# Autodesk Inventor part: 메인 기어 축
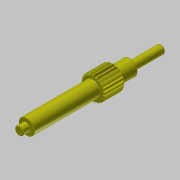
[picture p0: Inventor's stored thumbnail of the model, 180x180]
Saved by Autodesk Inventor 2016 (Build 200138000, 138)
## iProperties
Created: 2018-12
Part Number: 메인 기어 축
Material: 강철, 연강
Document SubType Name: Modeling
Designer: mduedu
Categories: <?xml version="1.0" encoding="UTF-16"?> <MemberInstance><Categories><FamilyTemplate><FamilyTemplateParameter ValueType="xs:double" Id="1" ObjectReferenceKey="da
Density: 7.86 g/cm^3
Appearance: 노란색
Mass: 179.676 g
Surface Area: 75.4119 cm^2
Volume: 22.8595 cm^3
CustomPartVersion: 1
Author: mduedu
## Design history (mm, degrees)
sketch "Sketch1"
  geometry: C1 r 11.3 at (0, 0)
  constraints: 1 centre point
  dimensions: "d0" = 22.6 diameter of C1 (= da_da)
extrude "Extrusion1" new body sketch "Sketch1" distance "d1" = 20 (= da_b); taper "d2" = 0 deg
workplane "Work Plane2"
sketch "Sketch2"
  geometry: C1 r 11.3 at (0, 0) reference; C2 r 10.5 at (0, 0)
  constraints: 1 centre point, 1 coincident
  dimensions: "d3" = 21 diameter of C2 (= da_dw)
feature "피치 지름" sketch "Sketch2" dims "d4" = 10, "d5" = 0
workplane "Work Plane8"
workplane "Work Plane9"
chamfer "모따기1" distance "d49" = 1; stored, may be unused: second distance "d50" = 2, angle "d51" = 45 deg
sketch "스케치3"
  geometry: C1 r 7.5 at (0, 0); 1 further point
  constraints: 1 centre point, 1 coincident
  dimensions: "d52" = 15 diameter of C1
extrude "돌출2" join sketch "스케치3" distance "d53" = 64; taper "d54" = 0 deg
sketch "스케치4"
  geometry: C1 r 4 at (0, 0); 1 further point
  constraints: 1 centre point, 1 coincident
  dimensions: "d55" = 8 diameter of C1
extrude "돌출3" join sketch "스케치4" distance "d56" = 7; taper "d57" = 0 deg
sketch "스케치5"
  geometry: C1 r 7.5 at (0, 0) reference; C2 r 7.5 at (0, 0) reference; 1 further point
extrude "돌출4" join sketch "스케치5" distance "d58" = 16; taper "d59" = 0 deg
sketch "스케치6"
  geometry: C1 r 4 at (0, 0); 1 further point
  constraints: 1 centre point, 1 coincident
  dimensions: "d60" = 8 diameter of C1
extrude "돌출5" join sketch "스케치6" distance "d61" = 30; taper "d62" = 0 deg
chamfer "모따기2" distance "d63" = 0.5; stored, may be unused: second distance "d64" = 2, angle "d65" = 45 deg
fillet "모깎기1" dims "d66" = 0.5
feature "스퍼 기어" dims "da_b" = 20, "da_d" = 21, "da_aw" = 31, "da_da" = 22.6, "da_df" = 19.086, "da_dw" = 21, angle "da_beta" = 0 deg, "da_lefttooth" = 0, "da_righttooth" = 0
sketch "스케치7" dims "d67" = 18
  geometry: C1 r 0.25 at (0, -9); 2 further points
  constraints: 2 vertical alignment, 1 centre point, 1 coincident, 2 other
  dimensions: "d68" = 0.5 diameter of C1
extrude "돌출6" join sketch "스케치7" distance "d69" = 0.3; taper "d70" = 0 deg
body "Solid1"
body "Srf1"
node "투영된 루프1"
other parameters: "d16" = 31 (= da_aw), "d17" = 0, "d34" = 1.496 (computed from da_z), "d39" = 0, "d41" = 0, "d43" = 31 (= da_aw), "d46" = 31 (= da_aw), "d47" = 0, "d48" = 0
